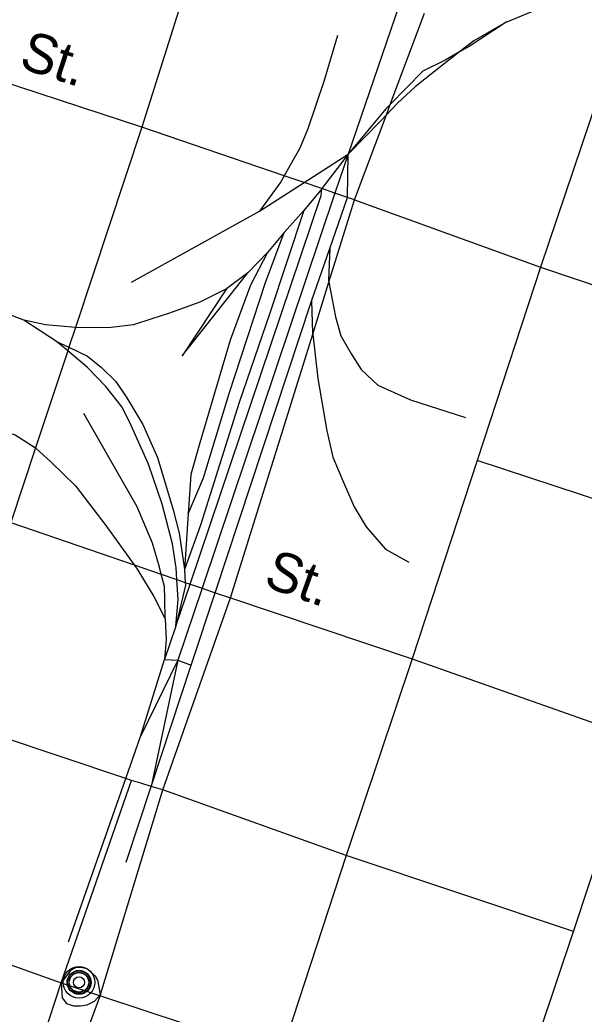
# Model space of a CAD drawing. Extents: x 2260773 to 2342389, y 552869 to 618546.
# Drawn here: x 2299105 to 2300461, y 596757 to 599147 of the extents above; entities that cross this region are included whole.
import ezdxf

# ---------------------------------------------------------------- set-up
doc = ezdxf.new("R2010")
doc.units = 0
for name, color, linetype in [('Exist Civil Demographics Community CELL', 7, 'Continuous'), ('Exist Civil Demographics County Seat CELL', 7, 'Continuous'), ('Exist Railroad Mainline', 7, 'Continuous'), ('Exist Railroad Siding', 7, 'Continuous'), ('Exist Road Non-System Type 51', 7, 'Continuous'), ('Exist Road Non-System Type 51 Label', 7, 'Continuous'), ('Exist Road Primary US Attributed', 7, 'Continuous'), ('Exist Road Primary US UnDivided 4 Lane Attributed', 7, 'Continuous')]:
    doc.layers.add(name, color=color, linetype=linetype)

msp = doc.modelspace()

# ---------------------------------------------------------------- linework, layer by layer
at = {"layer": 'Exist Civil Demographics Community CELL'}
msp.add_lwpolyline([(2299223.5, 596837.5), (2299223.8, 596839.2), (2299224.3, 596841.2), (2299225.2, 596843.4), (2299226.1, 596845.2), (2299227.1, 596846.9), (2299228.3, 596848.5), (2299229.5, 596849.8), (2299230.9, 596851.2), (2299232.5, 596852.6), (2299234.2, 596853.7), (2299235.7, 596854.6), (2299237.2, 596855.3), (2299238.9, 596856), (2299240.6, 596856.6), (2299241.9, 596856.9), (2299243.4, 596857.2), (2299244.7, 596857.4), (2299246.6, 596857.5), (2299248, 596857.4), (2299249.7, 596857.4), (2299251.2, 596857.1), (2299252.7, 596856.8), (2299254.2, 596856.4), (2299255.8, 596855.8), (2299257.8, 596854.9), (2299259.7, 596853.9), (2299261.3, 596852.8), (2299262.8, 596851.6), (2299263.8, 596850.6), (2299265.1, 596849.3), (2299266.3, 596847.8), (2299267.2, 596846.4), (2299268.2, 596844.9), (2299268.9, 596843.3), (2299269.5, 596841.8), (2299270, 596840.3), (2299270.4, 596838.9), (2299270.7, 596837), (2299270.9, 596835.6), (2299271, 596833.8), (2299270.9, 596832), (2299270.8, 596830.3), (2299270.5, 596828.6), (2299270, 596826.7), (2299269.4, 596824.9), (2299268.7, 596823.4), (2299267.7, 596821.6), (2299266.7, 596819.9), (2299265.7, 596818.5), (2299264.4, 596817.1), (2299262.8, 596815.6), (2299261.3, 596814.3), (2299259.7, 596813.3), (2299258.4, 596812.5), (2299256.3, 596811.5), (2299254.2, 596810.7), (2299252.4, 596810.2), (2299250.3, 596809.8), (2299249, 596809.7), (2299247.6, 596809.6), (2299245.9, 596809.6), (2299244.6, 596809.7), (2299242.9, 596810), (2299241.1, 596810.4), (2299239.7, 596810.8), (2299238.1, 596811.3), (2299236.7, 596811.9), (2299235.5, 596812.6), (2299233.5, 596813.9), (2299231.8, 596815.2), (2299230.3, 596816.5), (2299228.9, 596818), (2299227.9, 596819.2), (2299227, 596820.5), (2299225.8, 596822.7), (2299225.2, 596823.7), (2299224.7, 596825), (2299223.9, 596827.5), (2299223.5, 596829.6), (2299223.3, 596831.2), (2299223.2, 596833.1), (2299223.1, 596834.5), (2299223.3, 596836.5)], close=True, dxfattribs=at)
for centre, radius in [((2299247.1, 596833.7), 28.8), ((2299247, 596833.8), 23.4)]:
    msp.add_circle(centre, radius, dxfattribs=at)
at = {"layer": 'Exist Civil Demographics County Seat CELL'}
for radius in [38, 27.4, 13.2]:
    msp.add_circle((2299247.1, 596833.7), radius, dxfattribs=at)
at = {"layer": 'Exist Railroad Mainline'}
for p, q in [((2300016.7, 599182.2), (2299893.5, 598823.6)), ((2299830.4, 598740.8), (2299786.9, 598688.4)), ((2299786.9, 598688.4), (2299739.7, 598635.9)), ((2299739.7, 598635.9), (2299700.2, 598587.5)), ((2299700.2, 598587.5), (2299652.8, 598539)), ((2299652.8, 598539), (2299601.1, 598500.5)), ((2299192.7, 598374.1), (2299114.2, 598425.3)), ((2299479.9, 597689.5), (2299452.7, 597609.4)), ((2299394.8, 597424.8), (2299452.7, 597609.4)), ((2299484.8, 597607.7), (2299394.8, 597424.8))]:
    msp.add_line(p, q, dxfattribs=at)
for points in [[(2300273.9, 599141.4), (2300333.5, 599166.1), (2300401.4, 599190.8), (2300467.1, 599201.5), (2300559.1, 599202.4), (2300574.4, 599201.3), (2300659, 599195.4), (2300765.1, 599184.7), (2300879.3, 599165.9), (2301005.4, 599143.2), (2301103.5, 599126.4), (2301154.3, 599121.4)], [(2300273.9, 599141.4), (2300196, 599096.1), (2300161.7, 599069.5)], [(2300161.7, 599069.5), (2300124.6, 599040.8), (2300054.8, 598985.6), (2300012.6, 598946.7), (2299985.8, 598918.8), (2299970.4, 598902.8), (2299893.5, 598823.6)], [(2299893.5, 598823.6), (2299862.1, 598730.3), (2299543, 597780.9), (2299484.8, 597607.7)], [(2299893.5, 598823.6), (2299830.6, 598741.1), (2299830.4, 598740.8)], [(2299114.2, 598425.3), (2299032, 598456.4), (2298861.4, 598508.5), (2298779.1, 598532.2)], [(2299601.1, 598500.5), (2299537.4, 598467.9), (2299461.9, 598441), (2299422, 598428.6), (2299378.1, 598414.2), (2299324.2, 598407.6), (2299252.2, 598406.7), (2299238.7, 598407.8), (2299166.3, 598413.8), (2299114.2, 598425.3)], [(2299479.9, 597689.5), (2299485.3, 597753.6), (2299482.2, 597801.8), (2299480.4, 597829.6), (2299471.7, 597887.5), (2299446.8, 597983.1), (2299413.7, 598078.8), (2299372.7, 598172.1), (2299350.4, 598216), (2299311.7, 598265.5), (2299267.3, 598311.1), (2299219.9, 598351.1), (2299192.7, 598374.1)], [(2299222.1, 596931.1), (2299359.5, 597323.8), (2299394.8, 597424.8)]]:
    msp.add_lwpolyline(points, dxfattribs=at)
at = {"layer": 'Exist Railroad Siding'}
for p, q in [((2299373, 598516), (2299681, 598687.3)), ((2299805.4, 598470.7), (2299849.9, 598597.1)), ((2299509, 597959.8), (2299500.4, 597825.8)), ((2299484.8, 597607.7), (2299420.4, 597304.8)), ((2299452.7, 597609.4), (2299484.8, 597607.7)), ((2299484.8, 597607.7), (2299516.9, 597596)), ((2299420.4, 597304.8), (2299516.9, 597596)), ((2299360, 597122.5), (2299420.4, 597304.8))]:
    msp.add_line(p, q, dxfattribs=at)
for points in [[(2300273.9, 599141.4), (2300184.5, 599082.4), (2300161.7, 599069.5)], [(2299868.3, 599109), (2299835.6, 598998.7), (2299796.8, 598884.5), (2299777.5, 598838.3), (2299753.8, 598795.9), (2299740.3, 598771.9), (2299732.3, 598757.8), (2299681, 598687.3)], [(2300161.7, 599069.5), (2300127, 599049.9), (2300073.3, 599023.3)], [(2300073.3, 599023.3), (2299995, 598943.4), (2299984.3, 598932.5), (2299893.5, 598823.6)], [(2299681, 598687.3), (2299787.7, 598755.7), (2299893.5, 598823.6)], [(2299849.9, 598597.1), (2299892.5, 598720), (2299893.5, 598823.6)], [(2299479.9, 597689.5), (2299514, 597790.9), (2299828.7, 598724.9), (2299830.4, 598740.8)], [(2299786.9, 598688.4), (2299705.7, 598441.7), (2299632, 598227), (2299539.3, 597932.2), (2299500.4, 597825.8)], [(2299509, 597959.8), (2299546.1, 598046.1), (2299607.9, 598248.7), (2299694.9, 598515.5), (2299739.7, 598635.9)], [(2299700.2, 598587.5), (2299659, 598509.2), (2299610.5, 598376.6), (2299537.1, 598130), (2299516, 598053.9), (2299509, 597959.8)], [(2299849.9, 598597.1), (2299846.7, 598521.2), (2299847.6, 598516.5), (2299863.7, 598433.3), (2299876.1, 598387.6), (2299900.6, 598345.7), (2299925, 598306.1), (2299965.4, 598268.5), (2300043.8, 598233.3), (2300176.2, 598190.8)], [(2299601.1, 598500.5), (2299495, 598339.5), (2299652.8, 598539)], [(2299516.9, 597596), (2299574.3, 597770.2), (2299805.4, 598470.7)], [(2299805.4, 598470.7), (2299808.2, 598394.8), (2299808.6, 598391.5), (2299821.3, 598284.9), (2299842.6, 598159.3), (2299857.3, 598095.5), (2299883.9, 598031.8), (2299908.6, 597976.2), (2299937.1, 597928.3), (2299983.7, 597875), (2300040, 597843.6)], [(2299192.7, 598374.1), (2299222.8, 598359.8), (2299267, 598338.9), (2299301.3, 598311.3), (2299335.7, 598277.7), (2299362.1, 598238.1), (2299400.6, 598174.5), (2299435.5, 598094.8), (2299473, 597969.3), (2299487.4, 597913.5), (2299500.4, 597825.8)], [(2298872.6, 598222.7), (2299063, 598158.8), (2299093.2, 598149.2), (2299142.8, 598118.2), (2299143.5, 598117.8), (2299179.9, 598084.1), (2299238.4, 598026.8), (2299311.5, 597931.6), (2299379.3, 597837.1), (2299388.4, 597824.5), (2299427.2, 597761), (2299453.8, 597707.3)], [(2299453.8, 597707.3), (2299453.2, 597755.3), (2299452.8, 597785.3), (2299444.8, 597814.6), (2299440.3, 597831.2), (2299423.8, 597888.9), (2299386.9, 597976.4), (2299258.5, 598200.9)], [(2299500.4, 597825.8), (2299502.4, 597794.8), (2299502.9, 597787.9), (2299479.9, 597689.5)], [(2299453.8, 597707.3), (2299456.2, 597657.4), (2299452.7, 597609.4)]]:
    msp.add_lwpolyline(points, dxfattribs=at)
at = {"layer": 'Exist Road Non-System Type 51'}
for p, q in [((2299539.2, 599337.1), (2299398.1, 598888.7)), ((2299995, 598943.4), (2300076.9, 599162.7)), ((2299398.1, 598888.7), (2298951.8, 599035.4)), ((2299985.8, 598918.8), (2299995, 598943.4)), ((2299909.3, 598714.2), (2299985.8, 598918.8)), ((2299398.1, 598888.7), (2299238.7, 598407.8)), ((2299740.3, 598771.9), (2299398.1, 598888.7)), ((2299787.7, 598755.7), (2299740.3, 598771.9)), ((2299830.6, 598741.1), (2299787.7, 598755.7)), ((2299862.1, 598730.3), (2299830.6, 598741.1)), ((2299892.5, 598720), (2299862.1, 598730.3)), ((2299909.3, 598714.2), (2299892.5, 598720)), ((2299847.6, 598516.5), (2299909.3, 598714.2)), ((2299909.3, 598714.2), (2300356.3, 598552.4)), ((2300356.3, 598552.4), (2300203.6, 598087.8)), ((2300356.3, 598552.4), (2300906.4, 598365.8)), ((2299808.6, 598391.5), (2299847.6, 598516.5)), ((2299238.7, 598407.8), (2299222.8, 598359.8)), ((2299610.8, 597757.6), (2299808.6, 598391.5)), ((2299219.9, 598351.1), (2299142.8, 598118.2)), ((2299222.8, 598359.8), (2299219.9, 598351.1)), ((2299142.8, 598118.2), (2299083.3, 597938.7)), ((2300203.6, 598087.8), (2300048, 597611.5)), ((2300752.1, 597907.5), (2300203.6, 598087.8)), ((2299083.3, 597938.7), (2299379.3, 597837.1)), ((2299379.3, 597837.1), (2299444.8, 597814.6)), ((2299444.8, 597814.6), (2299482.2, 597801.8)), ((2299482.2, 597801.8), (2299502.4, 597794.8)), ((2299502.4, 597794.8), (2299514, 597790.9)), ((2299514, 597790.9), (2299543, 597780.9)), ((2299543, 597780.9), (2299574.3, 597770.2)), ((2299574.3, 597770.2), (2299610.8, 597757.6)), ((2299448.3, 597296.3), (2299610.8, 597757.6)), ((2299610.8, 597757.6), (2300048, 597611.5)), ((2300048, 597611.5), (2299889.4, 597138.6)), ((2300048, 597611.5), (2300588.8, 597420.3)), ((2299359.5, 597323.8), (2298923.7, 597469.7)), ((2299203.8, 596832.4), (2299372.9, 597319.2)), ((2299372.9, 597319.2), (2299359.5, 597323.8)), ((2299395.2, 597312.5), (2299372.9, 597319.2)), ((2299420.4, 597304.8), (2299395.2, 597312.5)), ((2299298.6, 596804.6), (2299448.3, 597296.3)), ((2299448.3, 597296.3), (2299420.4, 597304.8)), ((2299889.4, 597138.6), (2299448.3, 597296.3)), ((2299889.4, 597138.6), (2299732, 596658.9)), ((2300435.5, 596955.8), (2299889.4, 597138.6)), ((2299044.9, 596346), (2299203.8, 596832.4)), ((2299298.6, 596804.6), (2299117.2, 596319))]:
    msp.add_line(p, q, dxfattribs=at)
for points in [[(2300574.4, 599201.3), (2300534.2, 599078.4), (2300356.3, 598552.4)], [(2299298.6, 596804.6), (2299292.7, 596836), (2299287.1, 596847.9), (2299273.7, 596859.5), (2299265.8, 596866.4), (2299251.4, 596869.2), (2299238.2, 596868.4), (2299226.4, 596862.5), (2299203.8, 596832.4)], [(2299203.8, 596832.4), (2299206.7, 596796.5), (2299216.6, 596782.7), (2299233.9, 596777.3), (2299250.2, 596777.5), (2299266.2, 596779.7), (2299284.3, 596788.3), (2299298.6, 596804.6)]]:
    msp.add_lwpolyline(points, dxfattribs=at)
at = {"layer": 'Exist Road Primary US Attributed'}
for points in [[(2300273.8, 596473.9), (2300435.5, 596955.8), (2300588.8, 597420.3), (2300752.1, 597907.5), (2300906.4, 598365.8), (2301013.4, 598691.8), (2301154.3, 599121.4)], [(2298318.4, 597128.8), (2298768.6, 596988.4), (2299203.8, 596832.4)]]:
    msp.add_lwpolyline(points, dxfattribs=at)
at = {"layer": 'Exist Road Primary US UnDivided 4 Lane Attributed'}
msp.add_line((2299203.8, 596832.4), (2299732, 596658.9), dxfattribs=at)

# ---------------------------------------------------------------- texts
at = {"layer": 'Exist Road Non-System Type 51 Label'}
for rotation, p in [(341.9905, (2299099.6, 599032.8)), (340.3982, (2299687.4, 597787))]:
    msp.add_text('St.', height=95, rotation=rotation, dxfattribs=at).set_placement(p)

doc.saveas('drawing.dxf')
